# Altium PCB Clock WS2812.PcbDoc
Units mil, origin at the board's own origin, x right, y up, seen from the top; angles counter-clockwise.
Board outline 9400.03 x 3880.03 mil, 2 copper layers (Top Layer, Bottom Layer); 88 components, 89 nets, 350 pads, 0 vias.
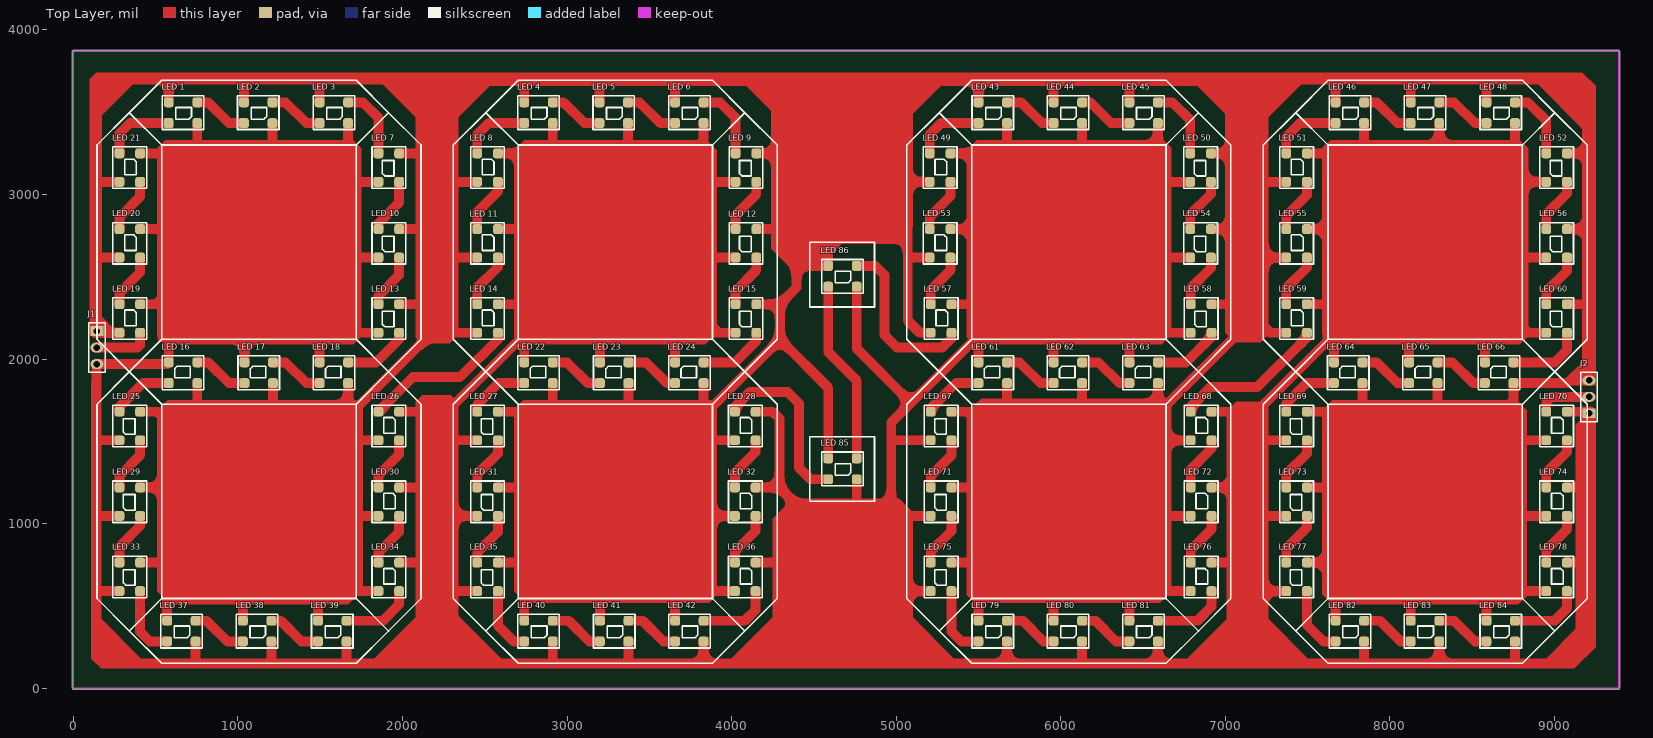
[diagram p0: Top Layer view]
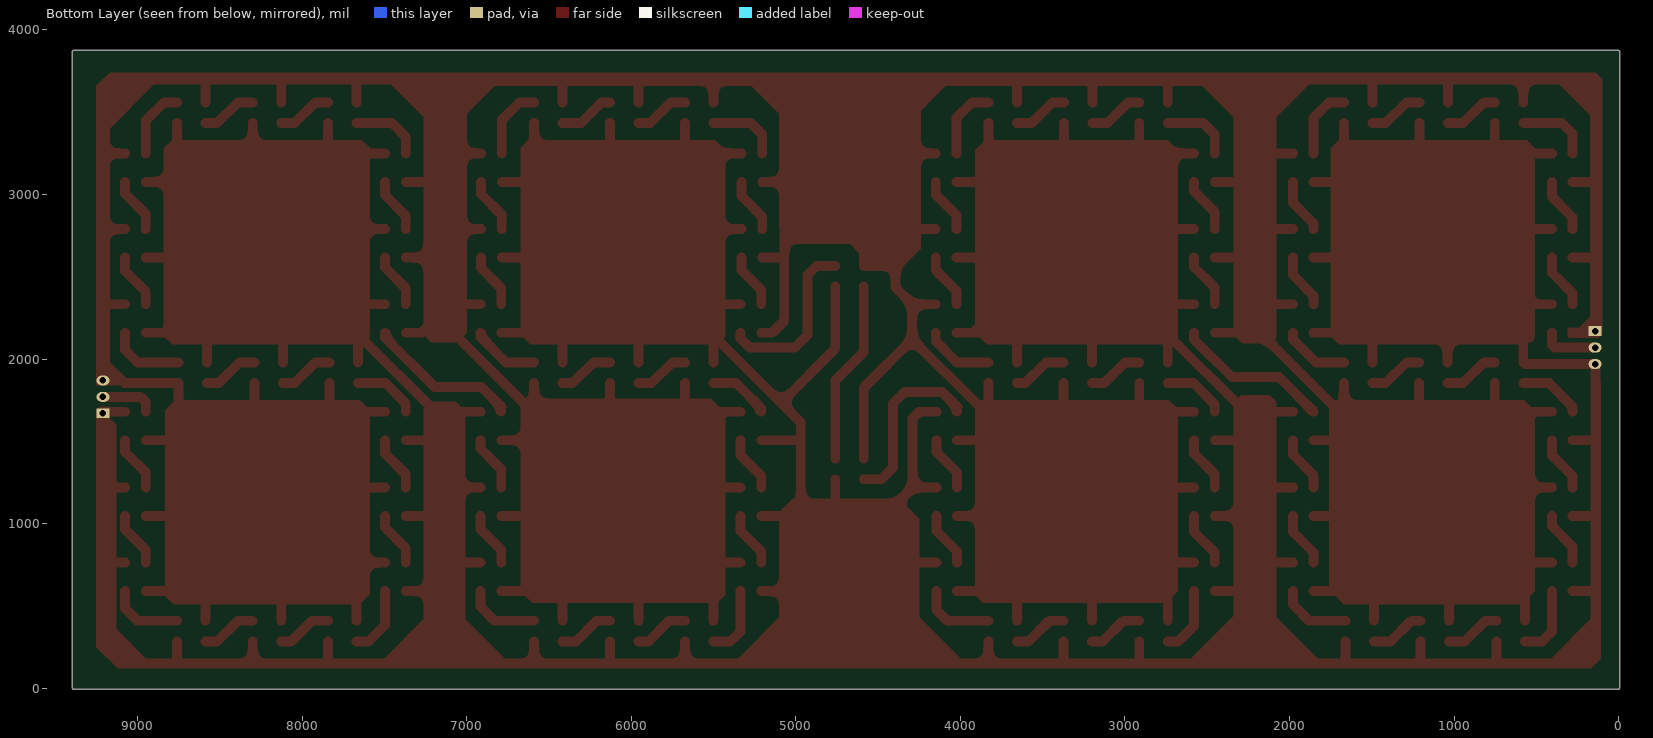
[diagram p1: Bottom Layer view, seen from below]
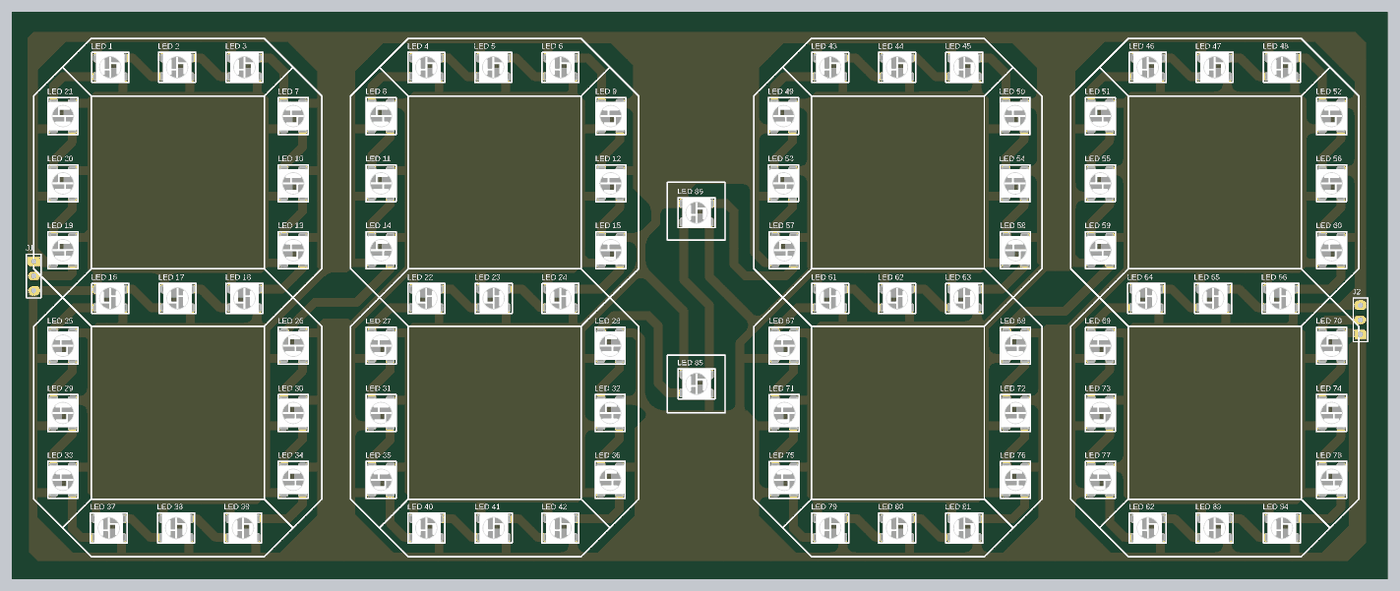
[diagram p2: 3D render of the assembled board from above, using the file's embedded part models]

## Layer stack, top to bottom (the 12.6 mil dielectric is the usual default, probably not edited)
Top Solder: solder mask 0.4, Solder Resist, Dk 3.5
Top Layer: signal copper 1.4
Dielectric 1: dielectric 12.6, FR-4, Dk 4.8
Bottom Layer: signal copper 1.4
Bottom Solder: solder mask 0.4, Solder Resist, Dk 3.5

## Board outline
0,-5.02 cw(c0,0) -5.01,0 -5.01,3870 cw(c0,3870) 0,3875.02 9390,3875.02 cw(c9390,3870) 9395.01,3870 9395.01,0 cw(c9390,0) 9390,-5.02

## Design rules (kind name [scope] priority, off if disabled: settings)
Clearance [All] p1: gap=10 ignorepadtopadclearanceinfootprint=FALSE except(0: Arc-Hole Track-Hole SMDPad-Hole THPad-Hole Via-Hole Fill-Hole Poly-Hole Region-Hole Text-Hole)
PolygonConnect [All] p1: connectstyle=Relief reliefconductorwidth=10 reliefentries=4 polygonreliefangle="90 Angle" airgapwidth=10
RoutingVias [All] p1: holewidth=28 width=50 viastyle="Through Hole" minholewidth=28 minwidth=50 maxholewidth=28 maxwidth=50
SolderMaskExpansion [All] p1: expansion=4
Width [All] p1: maxlimit=60 minlimit=10 preferedwidth=30
30 further rules are at their usual default settings.

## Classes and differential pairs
component class Sch_Min: J2 "LED 43" "LED 44" "LED 45" "LED 46" "LED 47" "LED 48" "LED 49" "LED 50" "LED 51" "LED 52" "LED 53" "LED 54" "LED 55" "LED 56" "LED 57" "LED 58" "LED 59" "LED 60" "LED 61" "LED 62" "LED 63" "LED 64" "LED 65" "LED 66" "LED 67" "LED 68" "LED 69" "LED 70" "LED 71" "LED 72" "LED 73" "LED 74" "LED 75" "LED 76" "LED 77" "LED 78" "LED 79" "LED 80" "LED 81" "LED 82" "LED 83" "LED 84"
component class Sch_Hour: J1 "LED 1" "LED 2" "LED 3" "LED 4" "LED 5" "LED 6" "LED 7" "LED 8" "LED 9" "LED 10" "LED 11" "LED 12" "LED 13" "LED 14" "LED 15" "LED 16" "LED 17" "LED 18" "LED 19" "LED 20" "LED 21" "LED 22" "LED 23" "LED 24" "LED 25" "LED 26" "LED 27" "LED 28" "LED 29" "LED 30" "LED 31" "LED 32" "LED 33" "LED 34" "LED 35" "LED 36" "LED 37" "LED 38" "LED 39" "LED 40" "LED 41" "LED 42" "LED 85" "LED 86"

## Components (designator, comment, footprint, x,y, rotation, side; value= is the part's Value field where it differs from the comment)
J1 "2.54_3P" "jump don duc thang 2.54_3p" 143.23,2070 r270 top
J2 "2.54_3P" "jump don duc thang 2.54_3p" 9210,1770 r90 top
"LED 1" "WS2812" "LED WS2812" 753.23,3434.02 r180 top
"LED 2" "WS2812" "LED WS2812" 1210,3434.02 r180 top
"LED 3" "WS2812" "LED WS2812" 1670,3434.02 r180 top
"LED 4" "WS2812" "LED WS2812" 2913.23,3434.02 r180 top
"LED 5" "WS2812" "LED WS2812" 3370,3434.02 r180 top
"LED 6" "WS2812" "LED WS2812" 3830,3434.02 r180 top
"LED 7" "WS2812" "LED WS2812" 1854.02,3076.77 r90 top
"LED 8" "WS2812" "LED WS2812" 2580,3250 r270 top
"LED 9" "WS2812" "LED WS2812" 4024.02,3076.77 r90 top
"LED 10" "WS2812" "LED WS2812" 1854.02,2616.77 r90 top
"LED 11" "WS2812" "LED WS2812" 2580,2790 r270 top
"LED 12" "WS2812" "LED WS2812" 4024.02,2616.77 r90 top
"LED 13" "WS2812" "LED WS2812" 1854.02,2160 r90 top
"LED 14" "WS2812" "LED WS2812" 2580,2333.23 r270 top
"LED 15" "WS2812" "LED WS2812" 4024.02,2160 r90 top
"LED 16" "WS2812" "LED WS2812" 580,1980 r0 top
"LED 17" "WS2812" "LED WS2812" 1040,1980 r0 top
"LED 18" "WS2812" "LED WS2812" 1496.77,1980 r0 top
"LED 19" "WS2812" "LED WS2812" 405.98,2333.23 r270 top
"LED 20" "WS2812" "LED WS2812" 405.98,2790 r270 top
"LED 21" "WS2812" "LED WS2812" 405.98,3250 r270 top
"LED 22" "WS2812" "LED WS2812" 2740,1980 r0 top
"LED 23" "WS2812" "LED WS2812" 3200,1980 r0 top
"LED 24" "WS2812" "LED WS2812" 3656.77,1980 r0 top
"LED 25" "WS2812" "LED WS2812" 280,1506.77 r90 top
"LED 26" "WS2812" "LED WS2812" 1980,1680 r270 top
"LED 27" "WS2812" "LED WS2812" 2454.02,1506.77 r90 top
"LED 28" "WS2812" "LED WS2812" 4145.98,1680 r270 top
"LED 29" "WS2812" "LED WS2812" 280,1046.77 r90 top
"LED 30" "WS2812" "LED WS2812" 1980,1220 r270 top
"LED 31" "WS2812" "LED WS2812" 2454.02,1046.77 r90 top
"LED 32" "WS2812" "LED WS2812" 4145.98,1220 r270 top
"LED 33" "WS2812" "LED WS2812" 280,590 r90 top
"LED 34" "WS2812" "LED WS2812" 1980,763.23 r270 top
"LED 35" "WS2812" "LED WS2812" 2454.02,590 r90 top
"LED 36" "WS2812" "LED WS2812" 4145.98,763.23 r270 top
"LED 37" "WS2812" "LED WS2812" 743.23,284.02 r180 top
"LED 38" "WS2812" "LED WS2812" 1203.23,284.02 r180 top
"LED 39" "WS2812" "LED WS2812" 1660,284.02 r180 top
"LED 40" "WS2812" "LED WS2812" 2913.23,284.02 r180 top
"LED 41" "WS2812" "LED WS2812" 3373.23,284.02 r180 top
"LED 42" "WS2812" "LED WS2812" 3830,284.02 r180 top
"LED 43" "WS2812" "LED WS2812" 5673.23,3434.02 r180 top
"LED 44" "WS2812" "LED WS2812" 6130,3434.02 r180 top
"LED 45" "WS2812" "LED WS2812" 6590,3434.02 r180 top
"LED 46" "WS2812" "LED WS2812" 7843.23,3434.02 r180 top
"LED 47" "WS2812" "LED WS2812" 8300,3434.02 r180 top
"LED 48" "WS2812" "LED WS2812" 8760,3434.02 r180 top
"LED 49" "WS2812" "LED WS2812" 5330,3250 r270 top
"LED 50" "WS2812" "LED WS2812" 6786.77,3076.77 r90 top
"LED 51" "WS2812" "LED WS2812" 7495.98,3250 r270 top
"LED 52" "WS2812" "LED WS2812" 8950,3076.77 r90 top
"LED 53" "WS2812" "LED WS2812" 5330,2790 r270 top
"LED 54" "WS2812" "LED WS2812" 6786.77,2616.77 r90 top
"LED 55" "WS2812" "LED WS2812" 7495.98,2790 r270 top
"LED 56" "WS2812" "LED WS2812" 8950,2616.77 r90 top
"LED 57" "WS2812" "LED WS2812" 5335.98,2333.23 r270 top
"LED 58" "WS2812" "LED WS2812" 6790,2160 r90 top
"LED 59" "WS2812" "LED WS2812" 7495.98,2333.23 r270 top
"LED 60" "WS2812" "LED WS2812" 8950,2160 r90 top
"LED 61" "WS2812" "LED WS2812" 5500,1980 r0 top
"LED 62" "WS2812" "LED WS2812" 5956.77,1980 r0 top
"LED 63" "WS2812" "LED WS2812" 6416.77,1980 r0 top
"LED 64" "WS2812" "LED WS2812" 7660,1980 r0 top
"LED 65" "WS2812" "LED WS2812" 8116.77,1980 r0 top
"LED 66" "WS2812" "LED WS2812" 8576.77,1980 r0 top
"LED 67" "WS2812" "LED WS2812" 5210,1506.77 r90 top
"LED 68" "WS2812" "LED WS2812" 6915.98,1680 r270 top
"LED 69" "WS2812" "LED WS2812" 7370,1506.77 r90 top
"LED 70" "WS2812" "LED WS2812" 9075.98,1680 r270 top
"LED 71" "WS2812" "LED WS2812" 5210,1046.77 r90 top
"LED 72" "WS2812" "LED WS2812" 6915.98,1220 r270 top
"LED 73" "WS2812" "LED WS2812" 7370,1046.77 r90 top
"LED 74" "WS2812" "LED WS2812" 9075.98,1220 r270 top
"LED 75" "WS2812" "LED WS2812" 5210,590 r90 top
"LED 76" "WS2812" "LED WS2812" 6915.98,763.23 r270 top
"LED 77" "WS2812" "LED WS2812" 7370,590 r90 top
"LED 78" "WS2812" "LED WS2812" 9075.98,763.23 r270 top
"LED 79" "WS2812" "LED WS2812" 5673.23,284.02 r180 top
"LED 80" "WS2812" "LED WS2812" 6130,284.02 r180 top
"LED 81" "WS2812" "LED WS2812" 6590,284.02 r180 top
"LED 82" "WS2812" "LED WS2812" 7843.23,284.02 r180 top
"LED 83" "WS2812" "LED WS2812" 8300,284.02 r180 top
"LED 84" "WS2812" "LED WS2812" 8760,284.02 r180 top
"LED 85" "WS2812" "LED WS2812" 4760,1270 r180 top
"LED 86" "WS2812" "LED WS2812" 4760,2440 r180 top

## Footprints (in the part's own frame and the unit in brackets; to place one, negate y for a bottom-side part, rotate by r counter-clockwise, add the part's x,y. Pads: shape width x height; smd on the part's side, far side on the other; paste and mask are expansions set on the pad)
"jump don duc thang 2.54_3p" [mm]
  rect 1.5x2 hole 1: 1(-2.54,0)
  oval 1.5x2 hole 1: 2(0,0) 3(2.54,0)
  silkscreen extent -3.81,-1.27 3.81,1.27, body extent -3.81,-1.27 3.81,1.27, height 7
"LED WS2812" [mil]
  rrect50% 60x60 smd: 1(0,0) 2(0,-125.98) 3(173.23,-125.98) 4(173.23,0)
  silkscreen extent -39,-165 213,39, body extent -19,-160 192,34, height 67

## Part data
J1 J2: library part "Jump Don Duc Thang 2.54_3P", "C?m"
"LED 1" "LED 2" "LED 3" "LED 4" "LED 5" "LED 6" "LED 7" "LED 8" "LED 9" "LED 10" "LED 11" "LED 12" "LED 13" "LED 14" "LED 15" "LED 16" "LED 17" "LED 18" "LED 19" "LED 20" "LED 21" "LED 22" "LED 23" "LED 24" "LED 25" "LED 26" "LED 27" "LED 28" "LED 29" "LED 30" "LED 31" "LED 32" "LED 33" "LED 34" "LED 35" "LED 36" "LED 37" "LED 38" "LED 39" "LED 40" "LED 41" "LED 42" "LED 43" "LED 44" "LED 45" "LED 46" "LED 47" "LED 48" "LED 49" "LED 50" "LED 51" "LED 52" "LED 53" "LED 54" "LED 55" "LED 56" "LED 57" "LED 58" "LED 59" "LED 60" "LED 61" "LED 62" "LED 63" "LED 64" "LED 65" "LED 66" "LED 67" "LED 68" "LED 69" "LED 70" "LED 71" "LED 72" "LED 73" "LED 74" "LED 75" "LED 76" "LED 77" "LED 78" "LED 79" "LED 80" "LED 81" "LED 82" "LED 83" "LED 84" "LED 85" "LED 86": library part "LED WS2812"

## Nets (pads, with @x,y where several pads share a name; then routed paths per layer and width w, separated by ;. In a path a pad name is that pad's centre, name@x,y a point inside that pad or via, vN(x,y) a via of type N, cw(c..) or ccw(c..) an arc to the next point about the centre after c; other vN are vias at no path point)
+5: "LED 1.1" "LED 2.1" "LED 3.1" "LED 4.1" "LED 5.1" "LED 6.1" "LED 7.1" "LED 8.1" "LED 9.1" "LED 10.1" "LED 11.1" "LED 12.1" "LED 13.1" "LED 14.1" "LED 15.1" "LED 16.1" "LED 17.1" "LED 18.1" "LED 19.1" "LED 20.1" "LED 21.1" "LED 22.1" "LED 23.1" "LED 24.1" "LED 25.1" "LED 26.1" "LED 27.1" "LED 28.1" "LED 29.1" "LED 30.1" "LED 31.1" "LED 32.1" "LED 33.1" "LED 34.1" "LED 35.1" "LED 36.1" "LED 37.1" "LED 38.1" "LED 39.1" "LED 40.1" "LED 41.1" "LED 42.1" "LED 43.1" "LED 44.1" "LED 45.1" "LED 46.1" "LED 47.1" "LED 48.1" "LED 49.1" "LED 50.1" "LED 51.1" "LED 52.1" "LED 53.1" "LED 54.1" "LED 55.1" "LED 56.1" "LED 57.1" "LED 58.1" "LED 59.1" "LED 60.1" "LED 61.1" "LED 62.1" "LED 63.1" "LED 64.1" "LED 65.1" "LED 66.1" "LED 67.1" "LED 68.1" "LED 69.1" "LED 70.1" "LED 71.1" "LED 72.1" "LED 73.1" "LED 74.1" "LED 75.1" "LED 76.1" "LED 77.1" "LED 78.1" "LED 79.1" "LED 80.1" "LED 81.1" "LED 82.1" "LED 83.1" "LED 84.1" "LED 85.1" "LED 86.1" J1.3 J2.1 | length 54520.9
  Top Layer w60: 280,590 150,590 140,580 ; 280,1046.77 146.77,1046.77 140,1040 ; 280,1506.77 143.23,1506.77 140,1510 ; 405.98,2333.23 503.23,2333.23 ; 405.98,2790 530,2790 540,2800 ; 405.98,3250 520,3250 540,3270 ; 540,2130 540,2333.23 ; 696.77,2333.23 540,2333.23 ; 743.23,284.02 743.23,153.23 740,150 ; 753.23,3434.02 753.23,3303.23 750,3300 ; 1040,1980 1040,2120 ; 1203.23,284.02 1203.23,153.23 1200,150 ; 1210,3434.02 1210,3303.23 1213.23,3300 ; 1496.77,1980 1496.77,2113.23 1490,2120 ; 1660,284.02 1660,160 1670,150 ; 1670,3434.02 1670,3320 1690,3300 ; 1854.02,2160 1730,2160 1720,2150 ; 1854.02,2616.77 1726.77,2616.77 1720,2610 ; 1854.02,3076.77 1723.23,3076.77 1720,3080 ; 1980,763.23 2093.23,763.23 2110,780 ; 1980,1220 2100,1220 2110,1210 ; 1980,1680 2110,1680 ; 2454.02,590 2320,590 2310,600 ; 2454.02,1046.77 2310,1046.77 ; 2454.02,1506.77 2316.77,1506.77 2310,1500 ; 2580,2333.23 2706.77,2333.23 2710,2330 ; 2580,2790 2700,2790 2710,2800 ; 2580,3250 2710,3250 ; 2740,1980 2740,2100 2720,2120 ; 2913.23,284.02 2913.23,153.23 2910,150 ; 2913.23,3434.02 2913.23,3306.77 2920,3300 ; 3200,1980 3200,2116.77 3196.77,2120 ; 3370,3434.02 3370,3310 3380,3300 ; 3373.23,284.02 3373.23,156.77 3380,150 ; 3656.77,1980 3656.77,2103.23 3640,2120 ; 3830,284.02 3830,150 ; 3830,3434.02 3830,3330 3800,3300 ; 4024.02,2160 3920,2160 ; 4024.02,2616.77 3883.23,2616.77 3880,2620 ; 4024.02,3076.77 3886.77,3076.77 3880,3070 ; 4145.98,763.23 4263.23,763.23 4280,780 ; 4145.98,1220 4290,1220 ; 4145.98,1680 4250,1680 4290,1640 4290,1220 ; 4760,1270 4760,1130 4750,1120 ; 4760,2440 4760,2064.02 5090,1734.02 ; 5210,590 5070,590 ; 5210,1046.77 5033.23,1046.77 ; 5210,1506.77 4983.23,1506.77 4970,1520 ; 5330,2790 5460,2790 ; 5330,3250 5460,3250 ; 5335.98,2333.23 5456.77,2333.23 5460,2330 ; 5460,2145.98 5460,2330 ; 5500,1980 5500,2095.98 5475.98,2120 ; 5673.23,284.02 5673.23,150 ; 5673.23,3434.02 5673.23,3303.23 5670,3300 ; 5956.77,1980 5956.77,2106.77 5970,2120 ; 6130,284.02 6130,160 6140,150 ; 6130,3434.02 6130,3310 6120,3300 ; 6416.77,1980 6416.77,2103.23 6400,2120 ; 6590,284.02 6590,150 ; 6590,3434.02 6590,3300 ; 6786.77,2616.77 6643.23,2616.77 6640,2620 ; 6786.77,3076.77 6643.23,3076.77 6640,3080 ; 6790,2160 6660,2160 6640,2180 ; 6915.98,763.23 7033.23,763.23 7040,770 ; 6915.98,1220 7040,1220 ; 6915.98,1680 7030,1680 7040,1670 ; 7190,1710 7080,1710 7040,1670 ; 7370,590 7230,590 ; 7370,1046.77 7236.77,1046.77 7230,1040 ; 7370,1506.77 7233.23,1506.77 7230,1510 ; 7495.98,2333.23 7613.23,2333.23 7620,2340 ; 7495.98,2790 7620,2790 ; 7495.98,3250 7610,3250 7620,3240 ; 7620,2125.98 7620,2340 ; 7660,1980 7660,2090 7630,2120 ; 7843.23,284.02 7843.23,156.77 7850,150 ; 7843.23,3434.02 7843.23,3306.77 7850,3300 ; 8116.77,1980 8116.77,2116.77 8120,2120 ; 8300,284.02 8300,150 ; 8300,3434.02 8300,3300 ; 8576.77,1980 8576.77,2113.23 8570,2120 ; 8760,284.02 8760,160 8770,150 ; 8760,3434.02 8760,3310 8750,3300 ; 8950,2160 8840,2160 8810,2190 ; 8950,2616.77 8813.23,2616.77 8810,2620 ; 8950,3076.77 8810,3076.77 ; 9075.98,763.23 9196.77,763.23 9200,760 ; 9075.98,1220 9200,1220 ; 9075.98,1680 9200,1680 9200,1220 ; 140,580 140,1040 ; 140,580 140,410 400,150 740,150 ; 140,1040 140,1510 ; 140,1510 140,1970 J1.3 570,1970 580,1980 580,2110 570,2120 1040,2120 ; 503.23,2333.23 540,2333.23 ; 503.23,2333.23 540,2370 ; 540,2333.23 540,2370 ; 540,2370 540,2800 ; 540,2800 540,3270 ; 540,3270 570,3300 750,3300 ; 740,150 1200,150 ; 750,3300 1213.23,3300 ; 1040,2120 1490,2120 ; 1200,150 1670,150 ; 1213.23,3300 1690,3300 ; 1490,2120 1690,2120 1720,2150 ; 1670,150 1840,150 2110,420 2110,780 ; 1690,3300 1720,3270 1720,3080 ; 1720,2150 1720,2610 ; 1720,2610 1720,3080 ; 2110,780 2110,1210 ; 2110,1210 2110,1680 ; 2110,1680 2110,1724.02 2135.98,1750 2280,1750 2310,1720 ; 2310,600 2310,1046.77 ; 2310,600 2310,420 2580,150 2910,150 ; 2310,1046.77 2310,1500 ; 2310,1500 2310,1720 ; 2310,1720 2710,2120 2720,2120 ; 2710,2330 2710,2800 ; 2710,2330 2710,2130 2720,2120 ; 2710,2800 2710,3250 ; 2710,3250 2760,3300 2920,3300 ; 2720,2120 3196.77,2120 ; 2910,150 3380,150 ; 2920,3300 3380,3300 ; 3196.77,2120 3430,2120 ; 3380,150 3830,150 ; 3380,3300 3800,3300 ; 3430,2120 3640,2120 ; 3430,2120 3470,2160 3840,2160 ; 3640,2120 3800,2120 3840,2160 ; 3800,3300 3880,3220 3880,3070 ; 3830,150 4010,150 4280,420 4280,780 ; 3840,2160 3880,2200 ; 3840,2160 3920,2160 ; 3880,2200 3920,2160 ; 3880,2200 3880,2620 ; 3880,2620 3880,3070 ; 4280,780 4280,1010 4390,1120 ; 4290,1220 4390,1120 ; 4390,1120 4750,1120 ; 4750,1120 4970,1120 ; 4970,1120 4970,1520 ; 4970,1120 5033.23,1056.77 5033.23,1046.77 ; 4970,1520 4970,1614.02 5090,1734.02 ; 5033.23,1046.77 5070,1010 5070,590 ; 5070,590 5070,420 5340,150 5673.23,150 ; 5090,1734.02 5475.98,2120 ; 5460,2330 5460,2790 ; 5460,2790 5460,3250 ; 5460,3250 5510,3300 5670,3300 ; 5475.98,2120 5970,2120 ; 5670,3300 6120,3300 ; 5673.23,150 6140,150 ; 5970,2120 6400,2120 ; 6120,3300 6590,3300 ; 6140,150 6590,150 ; 6400,2120 6580,2120 6640,2180 ; 6590,150 6780,150 7040,410 7040,770 ; 6590,3300 6640,3250 6640,3080 ; 6640,2180 6640,2620 ; 6640,2620 6640,3080 ; 7040,770 7040,1220 ; 7040,1220 7040,1670 ; 7230,590 7230,1040 ; 7230,590 7230,410 7490,150 7850,150 ; 7230,1040 7230,1510 ; 7230,1510 7230,1670 7205,1695 7630,2120 ; 7620,2340 7620,2790 ; 7620,2790 7620,3240 ; 7620,3240 7680,3300 7850,3300 ; 7630,2120 8120,2120 ; 7850,150 8300,150 ; 7850,3300 8300,3300 ; 8120,2120 8570,2120 ; 8300,150 8770,150 ; 8300,3300 8750,3300 ; 8570,2120 8740,2120 8810,2190 ; 8750,3300 8810,3240 8810,3076.77 ; 8770,150 8965.98,150 9200,384.02 9200,760 ; 8810,2190 8810,2620 ; 8810,2620 8810,3076.77 ; 9200,760 9200,1220
GND: "LED 1.3" "LED 2.3" "LED 3.3" "LED 4.3" "LED 5.3" "LED 6.3" "LED 7.3" "LED 8.3" "LED 9.3" "LED 10.3" "LED 11.3" "LED 12.3" "LED 13.3" "LED 14.3" "LED 15.3" "LED 16.3" "LED 17.3" "LED 18.3" "LED 19.3" "LED 20.3" "LED 21.3" "LED 22.3" "LED 23.3" "LED 24.3" "LED 25.3" "LED 26.3" "LED 27.3" "LED 28.3" "LED 29.3" "LED 30.3" "LED 31.3" "LED 32.3" "LED 33.3" "LED 34.3" "LED 35.3" "LED 36.3" "LED 37.3" "LED 38.3" "LED 39.3" "LED 40.3" "LED 41.3" "LED 42.3" "LED 43.3" "LED 44.3" "LED 45.3" "LED 46.3" "LED 47.3" "LED 48.3" "LED 49.3" "LED 50.3" "LED 51.3" "LED 52.3" "LED 53.3" "LED 54.3" "LED 55.3" "LED 56.3" "LED 57.3" "LED 58.3" "LED 59.3" "LED 60.3" "LED 61.3" "LED 62.3" "LED 63.3" "LED 64.3" "LED 65.3" "LED 66.3" "LED 67.3" "LED 68.3" "LED 69.3" "LED 70.3" "LED 71.3" "LED 72.3" "LED 73.3" "LED 74.3" "LED 75.3" "LED 76.3" "LED 77.3" "LED 78.3" "LED 79.3" "LED 80.3" "LED 81.3" "LED 82.3" "LED 83.3" "LED 84.3" "LED 85.3" "LED 86.3" J1.1 J2.3 | length 56749.2
  Top Layer w60: 280,2160 230,2160 143.23,2246.77 143.23,2600 ; 280,2616.77 160,2616.77 143.23,2600 ; 280,3076.77 146.46,3076.77 143.23,3080 ; 405.98,763.23 536.77,763.23 540,760 ; 405.98,1220 540,1220 ; 405.98,1680 510,1680 ; 570,410 570,610 ; 580,3560 580,3700 ; 690,1680 570,1680 ; 753.23,1854.02 753.23,1743.23 730,1720 ; 1030,410 1030,530 1020,540 ; 1036.77,3560 1036.77,3693.23 1030,3700 ; 1213.23,1854.02 1213.23,1726.77 1220,1720 ; 1486.77,410 1486.77,523.23 1470,540 ; 1496.77,3560 1496.77,3686.77 1510,3700 ; 1610,590 1650,590 ; 1670,1854.02 1670,1720 ; 1710,1720 1670,1720 ; 1854.02,590 1650,590 ; 1854.02,1046.77 1736.77,1046.77 1730,1040 ; 1854.02,1506.77 1733.23,1506.77 1730,1510 ; 1980,2333.23 2103.23,2333.23 ; 1980,2790 2100,2790 ; 1980,3250 2100,3250 ; 2454.02,2160 2310,2160 ; 2454.02,2616.77 2313.23,2616.77 2310,2620 ; 2454.02,3076.77 2316.77,3076.77 2310,3070 ; 2580,763.23 2706.77,763.23 2710,760 ; 2580,1220 2700,1220 2710,1230 ; 2580,1680 2693.23,1680 2710,1663.23 ; 2740,410 2740,590 ; 2740,3560 2740,3680 2750,3690 ; 2913.23,1854.02 2913.23,1726.77 2920,1720 ; 3196.77,3560 3196.77,3666.77 3220,3690 ; 3200,410 3200,530 3180,550 ; 3373.23,1854.02 3373.23,1723.23 3370,1720 ; 3656.77,410 3656.77,543.23 3650,550 ; 3656.77,3560 3656.77,3683.23 3650,3690 ; 3830,1854.02 3830,1720 ; 4020,590 3840,590 ; 4020,1046.77 3880,1046.77 ; 4020,1506.77 3883.23,1506.77 3880,1510 ; 4150,2333.23 4293.23,2333.23 ; 4150,2790 4260,2790 4270,2800 ; 4150,3250 4270,3250 ; 4586.77,1395.98 4586.77,1826.14 4293.23,2119.69 ; 5204.02,2616.77 5073.23,2616.77 5070,2620 ; 5204.02,3076.77 5070,3076.77 ; 5210,2160 5143.23,2160 5070,2233.23 5070,2620 ; 5335.98,763.23 5456.77,763.23 5460,760 ; 5335.98,1220 5450,1220 5460,1210 ; 5335.98,1680 5430,1680 ; 5500,410 5500,600 ; 5500,3560 5500,3690 ; 5673.23,1854.02 5673.23,1736.77 5680,1730 ; 5956.77,410 5956.77,546.77 5960,550 ; 5956.77,3560 5956.77,3676.77 5970,3690 ; 6130,1854.02 6130,1740 6120,1730 ; 6416.77,410 6416.77,523.23 6390,550 ; 6416.77,3560 6416.77,3676.77 6430,3690 ; 6590,1854.02 6590,1730 ; 6640,1726.77 6640,1506.77 ; 6790,590 6590,590 ; 6790,1046.77 6643.23,1046.77 6640,1050 ; 6790,1506.77 6640,1506.77 ; 6912.76,2790 7030,2790 ; 6912.76,3250 7030,3250 ; 6915.98,2333.23 7026.77,2333.23 ; 7094.02,2150 7183.23,2150 7233.23,2200 ; 7370,2160 7273.23,2160 7233.23,2200 ; 7370,2616.77 7233.23,2616.77 ; 7370,3076.77 7240,3076.77 7233.23,3070 ; 7495.98,763.23 7620,763.23 ; 7495.98,1220 7611.61,1220 7620,1211.61 ; 7495.98,1680 7600,1680 7620,1660 ; 7670,410 7670,530 7680,540 ; 7670,3560 7670,3690 7660,3700 ; 7833.23,1854.02 7833.23,1723.23 7830,1720 ; 8126.77,410 8126.77,536.77 8130,540 ; 8126.77,3560 8126.77,3676.77 8150,3700 ; 8290,1854.02 8290,1740 8270,1720 ; 8586.77,410 8586.77,533.23 8580,540 ; 8586.77,3560 8586.77,3696.77 8590,3700 ; 8720,1710 8800,1630 8800,1500 ; 8950,590 8820,590 8800,610 ; 8950,1046.77 8816.77,1046.77 8800,1030 ; 8950,1506.77 8806.77,1506.77 8800,1500 ; 9075.98,2333.23 9193.23,2333.23 9200,2340 ; 9075.98,2790 9200,2790 ; 9075.98,3250 9200,3250 ; 143.23,2600 143.23,3080 ; 143.23,3080 143.23,3503.23 340,3700 580,3700 ; 510,1680 570,1680 ; 510,1680 540,1650 ; 540,680 540,760 ; 540,680 540,640 570,610 ; 540,680 570,650 570,610 ; 540,760 540,1220 ; 540,1220 540,1650 ; 540,1650 570,1680 ; 570,610 640,540 1020,540 ; 570,1680 610,1720 730,1720 ; 580,3700 1030,3700 ; 730,1720 1220,1720 ; 1020,540 1470,540 ; 1030,3700 1510,3700 ; 1220,1720 1670,1720 ; 1470,540 1600,540 1650,590 ; 1510,3700 1890,3700 2110,3480 2110,3260 ; 1650,590 1730,670 1730,1040 ; 1730,1040 1730,1510 ; 1730,1510 1730,1720 1740,1720 2150,2130 ; 2100,2790 2110,2790 ; 2100,2790 2110,2800 ; 2100,3250 2110,3250 ; 2100,3250 2110,3260 ; 2103.23,2333.23 2110,2333.23 ; 2103.23,2333.23 2110,2340 ; 2110,2333.23 2110,2340 ; 2110,2333.23 2110,2170 2150,2130 ; 2110,2333.23 2303.23,2333.23 2310,2340 ; 2110,2340 2110,2610 ; 2110,2610 2110,2790 ; 2110,2610 2120,2620 2310,2620 ; 2110,2790 2110,2800 ; 2110,2790 2300,2790 2310,2800 ; 2110,2800 2110,3070 ; 2110,3070 2110,3250 ; 2110,3070 2310,3070 ; 2110,3250 2310,3250 ; 2110,3250 2110,3260 ; 2150,2130 2280,2130 2310,2160 ; 2310,2160 2310,2340 ; 2310,2340 2310,2620 ; 2310,2620 2310,2800 ; 2310,2800 2310,3070 ; 2310,3070 2310,3250 ; 2310,3250 2310,3480 2520,3690 2750,3690 ; 2710,670 2710,760 ; 2710,670 2710,620 2740,590 ; 2710,670 2740,640 2740,590 ; 2710,760 2710,1230 ; 2710,1230 2710,1663.23 ; 2710,1663.23 2766.77,1720 2920,1720 ; 2740,590 2780,550 3180,550 ; 2750,3690 3220,3690 ; 2920,1720 3370,1720 ; 3180,550 3650,550 ; 3220,3690 3650,3690 ; 3370,1720 3830,1720 ; 3650,550 3710,550 ; 3650,3690 4120,3690 4270,3540 4270,3250 ; 3710,550 3800,550 3840,590 ; 3710,550 3750,590 3840,590 ; 3830,1720 3880,1720 ; 3840,590 3880,630 3880,1046.77 ; 3880,1046.77 3880,1510 ; 3880,1510 3880,1720 ; 3880,1720 3893.54,1720 4293.23,2119.69 ; 4270,2800 4270,3250 ; 4270,2800 4270,2690 4394.02,2565.98 ; 4293.23,2119.69 4293.23,2333.23 ; 4293.23,2333.23 4394.02,2434.02 4394.02,2565.98 ; 4394.02,2565.98 4586.77,2565.98 4586.77,2666.77 4650,2730 5070,2730 ; 5070,2620 5070,2730 ; 5070,2730 5070,3076.77 ; 5070,3076.77 5070,3520 5240,3690 5500,3690 ; 5430,1680 5490,1680 ; 5430,1680 5460,1650 ; 5460,760 5460,1210 ; 5460,760 5460,640 5500,600 ; 5460,1210 5460,1650 ; 5460,1650 5490,1680 ; 5490,1680 5540,1730 5630,1730 ; 5490,1680 5580,1680 5630,1730 ; 5500,600 5550,550 5960,550 ; 5500,3690 5970,3690 ; 5630,1730 5680,1730 ; 5680,1730 6120,1730 ; 5960,550 6390,550 ; 5970,3690 6430,3690 ; 6120,1730 6590,1730 ; 6390,550 6510,550 ; 6430,3690 6880,3690 7030,3540 7030,3250 ; 6510,550 6550,550 6590,590 ; 6510,550 6550,590 6590,590 ; 6590,590 6640,640 6640,1050 ; 6590,1730 6650,1730 7070,2150 7030,2190 7030,2330 ; 6640,1050 6640,1506.77 ; 7026.77,2333.23 7030,2333.23 ; 7026.77,2333.23 7030,2330 ; 7030,2330 7030,2333.23 ; 7030,2333.23 7030,2620 ; 7030,2333.23 7216.46,2333.23 7233.23,2350 ; 7030,2620 7030,2790 ; 7030,2620 7033.23,2616.77 7233.23,2616.77 ; 7030,2790 7030,3070 ; 7030,2790 7213.23,2790 7233.23,2810 ; 7030,3070 7030,3250 ; 7030,3070 7233.23,3070 ; 7030,3250 7233.23,3250 ; 7233.23,2200 7233.23,2350 ; 7233.23,2350 7233.23,2616.77 ; 7233.23,2616.77 7233.23,2810 ; 7233.23,2810 7233.23,3070 ; 7233.23,3070 7233.23,3250 ; 7233.23,3250 7233.23,3523.23 7410,3700 7660,3700 ; 7620,763.23 7620,1211.61 ; 7620,763.23 7620,600 7680,540 ; 7620,1211.61 7620,1660 ; 7620,1660 7680,1720 7830,1720 ; 7660,3700 8150,3700 ; 7680,540 8130,540 ; 7830,1720 8270,1720 ; 8130,540 8580,540 ; 8150,3700 8590,3700 ; 8270,1720 8720,1720 8750,1750 8750,1854.02 9080,1854.02 9200,1974.02 9200,2340 ; 8580,540 8730,540 8800,610 ; 8590,3700 9020,3700 9200,3520 9200,3250 ; 8800,610 8800,1030 ; 8800,1030 8800,1500 ; 9200,2340 9200,2790 ; 9200,2790 9200,3250
M-N: "LED 57.4" "LED 86.2" | length 1051.9
  Top Layer w60: 4760,2565.98 4874.02,2565.98 4930,2510 4930,2145.98 5005.98,2070 5280,2070 5335.98,2125.98 5335.98,2160
NetJ1_2: "LED 19.4" J1.2 | length 343.4
  Top Layer w60: J1.2 390,2070 405.98,2085.98 405.98,2160
NetJ2_2: "LED 70.2" J2.2 | length 332.4
  Top Layer w60: 8950,1680 8950,1740 8980,1770 J2.2
"NetLED 1_2": "LED 1.2" "LED 2.4" | length 335.7
  Top Layer w60: 753.23,3560 820,3560 945.98,3434.02 1036.77,3434.02
"NetLED 1_4": "LED 1.4" "LED 21.2" | length 446.5
  Top Layer w60: 280,3250 280,3370 344.02,3434.02 580,3434.02
"NetLED 2_2": "LED 2.2" "LED 3.4" | length 339
  Top Layer w60: 1210,3560 1290,3560 1415.98,3434.02 1496.77,3434.02
"NetLED 3_2": "LED 3.2" "LED 7.4" | length 438.9
  Top Layer w60: 1670,3560 1760,3560 1854.02,3465.98 1854.02,3250
"NetLED 4_2": "LED 4.2" "LED 5.4" | length 335.7
  Top Layer w60: 2913.23,3560 2980,3560 3105.98,3434.02 3196.77,3434.02
"NetLED 4_4": "LED 4.4" "LED 8.2" | length 429
  Top Layer w60: 2454.02,3250 2454.02,3364.02 2524.02,3434.02 2740,3434.02
"NetLED 5_2": "LED 5.2" "LED 6.4" | length 339
  Top Layer w60: 3370,3560 3440,3560 3565.98,3434.02 3656.77,3434.02
"NetLED 6_2": "LED 6.2" "LED 9.4" | length 448.9
  Top Layer w60: 3830,3560 3930,3560 4024.02,3465.98 4024.02,3250
"NetLED 7_2": "LED 7.2" "LED 10.4" | length 339
  Top Layer w60: 1854.02,2790 1854.02,2824.02 1980,2950 1980,3076.77
"NetLED 8_4": "LED 8.4" "LED 11.2" | length 339
  Top Layer w60: 2454.02,2790 2454.02,2894.02 2580,3020 2580,3076.77
"NetLED 9_2": "LED 9.2" "LED 12.4" | length 339
  Top Layer w60: 4024.02,2790 4024.02,2874.02 4150,3000 4150,3076.77
"NetLED 10_2": "LED 10.2" "LED 13.4" | length 335.7
  Top Layer w60: 1854.02,2333.23 1854.02,2384.02 1980,2510 1980,2616.77
"NetLED 11_4": "LED 11.4" "LED 14.2" | length 335.7
  Top Layer w60: 2454.02,2333.23 2454.02,2434.02 2580,2560 2580,2616.77
"NetLED 12_2": "LED 12.2" "LED 15.4" | length 335.7
  Top Layer w60: 4024.02,2333.23 4024.02,2414.02 4150,2540 4150,2616.77
"NetLED 13_2": "LED 13.2" "LED 18.4" | length 408
  Top Layer w60: 1670,1980 1840,1980 1980,2120 1980,2160
"NetLED 14_4": "LED 14.4" "LED 26.2" | length 948.2
  Top Layer w60: 1854.02,1680 2064.02,1890 2350,1890 2580,2120 2580,2160
"NetLED 15_2": "LED 15.2" "LED 24.4" | length 423.8
  Top Layer w60: 3830,1980 4020,1980 4150,2110 4150,2160
"NetLED 16_2": "LED 16.2" "LED 25.4" | length 389.7
  Top Layer w60: 280,1680 280,1710 424.02,1854.02 580,1854.02
"NetLED 16_4": "LED 16.4" "LED 17.2" | length 339
  Top Layer w60: 753.23,1980 820,1980 945.98,1854.02 1040,1854.02
"NetLED 17_4": "LED 17.4" "LED 18.2" | length 335.7
  Top Layer w60: 1213.23,1980 1290,1980 1415.98,1854.02 1496.77,1854.02
"NetLED 19_2": "LED 19.2" "LED 20.4" | length 335.7
  Top Layer w60: 280,2333.23 280,2400 405.98,2525.98 405.98,2616.77
"NetLED 20_2": "LED 20.2" "LED 21.4" | length 339
  Top Layer w60: 280,2790 280,2860 405.98,2985.98 405.98,3076.77
"NetLED 22_2": "LED 22.2" "LED 27.4" | length 383.8
  Top Layer w60: 2454.02,1680 2454.02,1724.02 2584.02,1854.02 2740,1854.02
"NetLED 22_4": "LED 22.4" "LED 23.2" | length 339
  Top Layer w60: 2913.23,1980 3000,1980 3125.98,1854.02 3200,1854.02
"NetLED 23_4": "LED 23.4" "LED 24.2" | length 335.7
  Top Layer w60: 3373.23,1980 3480,1980 3605.98,1854.02 3656.77,1854.02
"NetLED 25_2": "LED 25.2" "LED 29.4" | length 339
  Top Layer w60: 280,1220 280,1290 405.98,1415.98 405.98,1506.77
"NetLED 26_4": "LED 26.4" "LED 30.2" | length 339
  Top Layer w60: 1854.02,1220 1854.02,1294.02 1980,1420 1980,1506.77
"NetLED 27_2": "LED 27.2" "LED 31.4" | length 339
  Top Layer w60: 2454.02,1220 2454.02,1300 2580,1425.98 2580,1506.77
"NetLED 28_2": "LED 28.2" "LED 85.4" | length 1082
  Top Layer w60: 4020,1680 4020,1710 4110,1800 4340,1800 4410,1730 4410,1340 4480,1270 4586.77,1270
"NetLED 28_4": "LED 28.4" "LED 32.2" | length 339
  Top Layer w60: 4020,1220 4020,1310 4145.98,1435.98 4145.98,1506.77
"NetLED 29_2": "LED 29.2" "LED 33.4" | length 335.7
  Top Layer w60: 280,763.23 280,860 405.98,985.98 405.98,1046.77
"NetLED 30_4": "LED 30.4" "LED 34.2" | length 335.7
  Top Layer w60: 1854.02,763.23 1854.02,824.02 1980,950 1980,1046.77
"NetLED 31_2": "LED 31.2" "LED 35.4" | length 335.7
  Top Layer w60: 2454.02,763.23 2454.02,824.02 2580,950 2580,1046.77
"NetLED 32_4": "LED 32.4" "LED 36.2" | length 335.7
  Top Layer w60: 4020,763.23 4020,830 4145.98,955.98 4145.98,1046.77
"NetLED 33_2": "LED 33.2" "LED 37.4" | length 434.9
  Top Layer w60: 405.98,590 405.98,344.02 465.98,284.02 570,284.02
"NetLED 34_4": "LED 34.4" "LED 39.2" | length 442
  Top Layer w60: 1660,410 1881.01,410 1980,508.99 1980,590
"NetLED 35_2": "LED 35.2" "LED 40.4" | length 409.8
  Top Layer w60: 2580,590 2580,380 2675.98,284.02 2740,284.02
"NetLED 36_4": "LED 36.4" "LED 42.2" | length 457.3
  Top Layer w60: 3830,410 4080,410 4145.98,475.98 4145.98,590
"NetLED 37_2": "LED 37.2" "LED 38.4" | length 339
  Top Layer w60: 743.23,410 810,410 935.98,284.02 1030,284.02
"NetLED 38_2": "LED 38.2" "LED 39.4" | length 335.7
  Top Layer w60: 1203.23,410 1260,410 1385.98,284.02 1486.77,284.02
"NetLED 40_2": "LED 40.2" "LED 41.4" | length 339
  Top Layer w60: 2913.23,410 3010,410 3135.98,284.02 3200,284.02
"NetLED 41_2": "LED 41.2" "LED 42.4" | length 335.7
  Top Layer w60: 3373.23,410 3460,410 3585.98,284.02 3656.77,284.02
"NetLED 43_2": "LED 43.2" "LED 44.4" | length 335.7
  Top Layer w60: 5673.23,3560 5760,3560 5885.98,3434.02 5956.77,3434.02
"NetLED 43_4": "LED 43.4" "LED 49.2" | length 439
  Top Layer w60: 5204.02,3250 5204.02,3364.02 5274.02,3434.02 5500,3434.02
"NetLED 44_2": "LED 44.2" "LED 45.4" | length 339
  Top Layer w60: 6130,3560 6180,3560 6305.98,3434.02 6416.77,3434.02
"NetLED 45_2": "LED 45.2" "LED 50.4" | length 444.2
  Top Layer w60: 6590,3560 6680,3560 6786.77,3453.23 6786.77,3250
"NetLED 46_2": "LED 46.2" "LED 47.4" | length 335.7
  Top Layer w60: 7843.23,3560 7920,3560 8045.98,3434.02 8126.77,3434.02
"NetLED 46_4": "LED 46.4" "LED 51.2" | length 434.8
  Top Layer w60: 7370,3250 7370,3350 7454.02,3434.02 7670,3434.02
"NetLED 47_2": "LED 47.2" "LED 48.4" | length 339
  Top Layer w60: 8300,3560 8390,3560 8515.98,3434.02 8586.77,3434.02
"NetLED 48_2": "LED 48.2" "LED 52.4" | length 435.6
  Top Layer w60: 8760,3560 8840,3560 8950,3450 8950,3250
"NetLED 49_4": "LED 49.4" "LED 53.2" | length 339
  Top Layer w60: 5204.02,2790 5204.02,2864.02 5330,2990 5330,3076.77
"NetLED 50_2": "LED 50.2" "LED 54.4" | length 339
  Top Layer w60: 6786.77,2790 6786.77,2876.77 6912.76,3002.76 6912.76,3076.77
"NetLED 51_4": "LED 51.4" "LED 55.2" | length 339
  Top Layer w60: 7370,2790 7370,2870 7495.98,2995.98 7495.98,3076.77
"NetLED 52_2": "LED 52.2" "LED 56.4" | length 339
  Top Layer w60: 8950,2790 8950,2880 9075.98,3005.98 9075.98,3076.77
"NetLED 53_4": "LED 53.4" "LED 57.2" | length 333.2
  Top Layer w60: 5210,2333.23 5210,2420 5330,2540 5330,2616.77
"NetLED 54_2": "LED 54.2" "LED 58.4" | length 334.4
  Top Layer w60: 6790,2333.23 6790,2430 6912.76,2552.76 6912.76,2616.77
"NetLED 55_4": "LED 55.4" "LED 59.2" | length 335.7
  Top Layer w60: 7370,2333.23 7370,2430 7495.98,2555.98 7495.98,2616.77
"NetLED 56_2": "LED 56.2" "LED 60.4" | length 335.7
  Top Layer w60: 8950,2333.23 8950,2410 9075.98,2535.98 9075.98,2616.77
"NetLED 58_2": "LED 58.2" "LED 63.4" | length 414.6
  Top Layer w60: 6590,1980 6760,1980 6915.98,2135.98 6915.98,2160
"NetLED 59_4": "LED 59.4" "LED 68.2" | length 938.8
  Top Layer w60: 6790,1680 6790,1710 6910,1830 7194.02,1830 7495.98,2131.97 7495.98,2160
"NetLED 60_2": "LED 60.2" "LED 66.4" | length 461.5
  Top Layer w60: 8750,1980 9000,1980 9075.98,2055.98 9075.98,2160
"NetLED 61_2": "LED 61.2" "LED 67.4" | length 373.8
  Top Layer w60: 5210,1680 5210,1700 5364.02,1854.02 5500,1854.02
"NetLED 61_4": "LED 61.4" "LED 62.2" | length 335.7
  Top Layer w60: 5673.23,1980 5750,1980 5875.98,1854.02 5956.77,1854.02
"NetLED 62_4": "LED 62.4" "LED 63.2" | length 339
  Top Layer w60: 6130,1980 6230,1980 6355.98,1854.02 6416.77,1854.02
"NetLED 64_2": "LED 64.2" "LED 69.4" | length 391.4
  Top Layer w60: 7370,1680 7370,1730 7494.02,1854.02 7660,1854.02
"NetLED 64_4": "LED 64.4" "LED 65.2" | length 335.7
  Top Layer w60: 7833.23,1980 7920,1980 8045.98,1854.02 8116.77,1854.02
"NetLED 65_4": "LED 65.4" "LED 66.2" | length 339
  Top Layer w60: 8290,1980 8380,1980 8505.98,1854.02 8576.77,1854.02
"NetLED 67_2": "LED 67.2" "LED 71.4" | length 339
  Top Layer w60: 5210,1220 5210,1290 5335.98,1415.98 5335.98,1506.77
"NetLED 68_4": "LED 68.4" "LED 72.2" | length 339
  Top Layer w60: 6790,1220 6790,1330 6915.98,1455.98 6915.98,1506.77
"NetLED 69_2": "LED 69.2" "LED 73.4" | length 339
  Top Layer w60: 7370,1220 7370,1300 7495.98,1425.98 7495.98,1506.77
"NetLED 70_4": "LED 70.4" "LED 74.2" | length 339
  Top Layer w60: 8950,1220 8950,1310 9075.98,1435.98 9075.98,1506.77
"NetLED 71_2": "LED 71.2" "LED 75.4" | length 335.7
  Top Layer w60: 5210,763.23 5210,830 5335.98,955.98 5335.98,1046.77
"NetLED 72_4": "LED 72.4" "LED 76.2" | length 335.7
  Top Layer w60: 6790,763.23 6790,840 6915.98,965.98 6915.98,1046.77
"NetLED 73_2": "LED 73.2" "LED 77.4" | length 335.7
  Top Layer w60: 7370,763.23 7370,850 7495.98,975.98 7495.98,1046.77
"NetLED 74_4": "LED 74.4" "LED 78.2" | length 335.7
  Top Layer w60: 8950,763.23 8950,840 9075.98,965.98 9075.98,1046.77
"NetLED 75_2": "LED 75.2" "LED 79.4" | length 434.9
  Top Layer w60: 5335.98,590 5335.98,344.02 5395.98,284.02 5500,284.02
"NetLED 76_4": "LED 76.4" "LED 81.2" | length 455.6
  Top Layer w60: 6590,410 6830,410 6915.98,495.98 6915.98,590
"NetLED 77_2": "LED 77.2" "LED 82.4" | length 421.4
  Top Layer w60: 7495.98,590 7495.98,384.02 7595.98,284.02 7670,284.02
"NetLED 78_4": "LED 78.4" "LED 84.2" | length 451.5
  Top Layer w60: 8760,410 9000,410 9075.98,485.98 9075.98,590
"NetLED 79_2": "LED 79.2" "LED 80.4" | length 335.7
  Top Layer w60: 5673.23,410 5770,410 5895.98,284.02 5956.77,284.02
"NetLED 80_2": "LED 80.2" "LED 81.4" | length 339
  Top Layer w60: 6130,410 6210,410 6335.98,284.02 6416.77,284.02
"NetLED 82_2": "LED 82.2" "LED 83.4" | length 335.7
  Top Layer w60: 7843.23,410 7940,410 8065.98,284.02 8126.77,284.02
"NetLED 83_2": "LED 83.2" "LED 84.4" | length 339
  Top Layer w60: 8300,410 8390,410 8515.98,284.02 8586.77,284.02
"NetLED 85_2": "LED 85.2" "LED 86.4" | length 1115.8
  Top Layer w60: 4586.77,2440 4586.77,2043.23 4760,1870 4760,1395.98

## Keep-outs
Top Layer:
  lines w10: 0,0 9390,0 9390,3870 0,3870 0,3770 0,0

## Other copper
Top Layer:
  region net GND: 1760,600 1670,510 590,510 510,590 510,1686.77 573.23,1750 1700,1750 1760,1690
  region net GND: 3910,930 3910.3,930.3 3910.3,1709.7 3870,1750 2733.23,1750 2680,1696.77 2680,590 2750,520 3863.23,520 3910,566.77
  region net GND: 5476.77,520 5430,566.77 5430,1674.02 5515.98,1760 6620,1760 6670,1710 6670,590 6600,520
  region net GND: 7650,1750 7590,1690 7590,570 7650,510 8780,510 8830,560 8830,1690 8770,1750
  region net +5: 7636.46,3330 7590,3283.54 7590,2150 7650,2090 8790,2090 8840,2140 8840,3280 8790,3330
  region net +5: 6170,3330 5490,3330 5430,3270 5430,2134.02 5474.02,2090 6613.23,2090 6670,2146.77 6670,3283.23 6621.73,3331.5 6516.5,3331.5
  region net +5: 3850,3330 3910,3270 3910,2160 3840,2090 2720,2090 2680,2130 2680,3270 2740,3330
  region net +5: 510,3280 560,3330 1700,3330 1750,3280 1750,2140 1700,2090 560,2090 510,2140
  region net GND: 4670,2700 4610,2640 4610,2620 4555.98,2565.98 4344.02,2565.98 4240,2670 4240,2744.02 4360,2864.02
  region net GND: 4660,2700
  region net +5: 110,1860 110,180 170,120 9120,120 9250,250 9250,1690 9230,1710 9170,1710 9170,1640 9130,1600 9130,360 8950,180 7500,180 7260,420 7260,1700 7220,1740 7066.77,1740 7010,1683.23 7010,420 6770,180 5350,180 5100,430 5100,1070 5020,1150 4370,1150 4250,1030 4250,430 4000,180 2600,180 2340,440 2340,1733.23 2293.23,1780 2120,1780 2080,1740 2080,430 1830,180 410,180 170,420 170,1860 160,1870 120,1870
  region net GND: 300,2130 120,2130 100,2150 100,3700 140,3740 4220,3740 5110,3740 9170,3740 9250,3660 9250,1840 9075.98,1840 9075.98,1885.98 9170,1980 9170,3400 8900,3670 7460,3670 7260,3470 7260,2146.77 7216.46,2103.23 7056.77,2103.23 7000,2160 7000,3490 6830,3660 5270,3660 5100,3490 5100,2800 5000,2700 4290,2700 4240,2750 4240,3510 4090,3660 2530,3660 2340,3470 2340,2150 2286.18,2096.18 2113.82,2096.18 2080,2130 2080,3470 1880,3670 360,3670 170,3480 170,2240 220,2190 300,2190 310,2180 310,2140

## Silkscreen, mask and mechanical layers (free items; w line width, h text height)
Top Overlay:
  drawing of 201 lines, arcs and shapes, not listed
